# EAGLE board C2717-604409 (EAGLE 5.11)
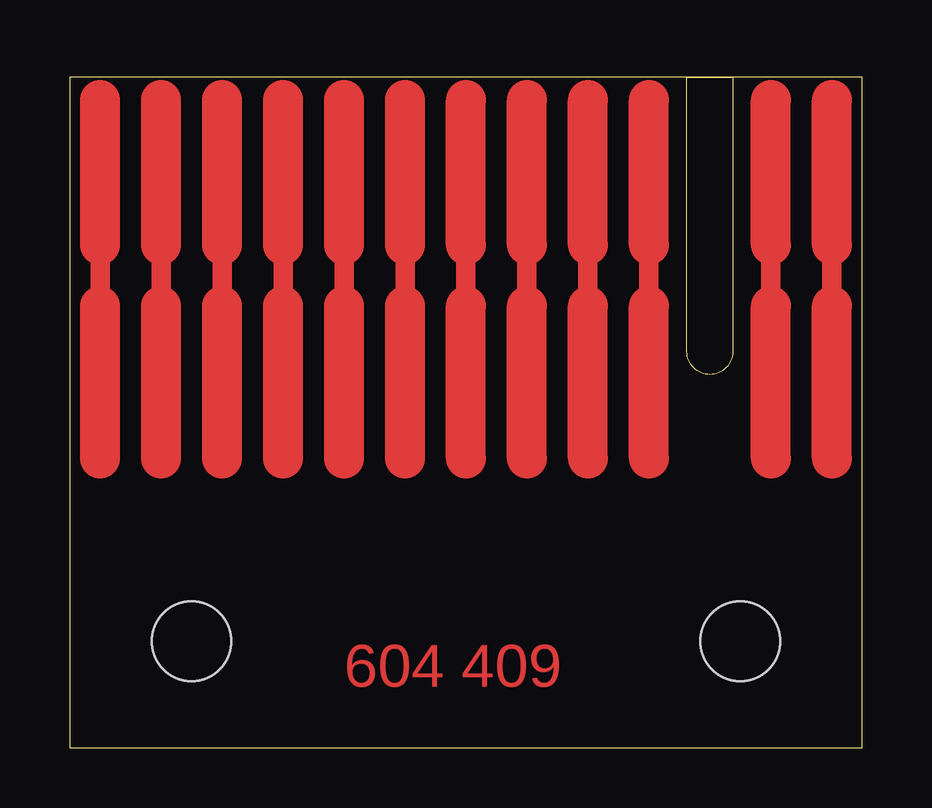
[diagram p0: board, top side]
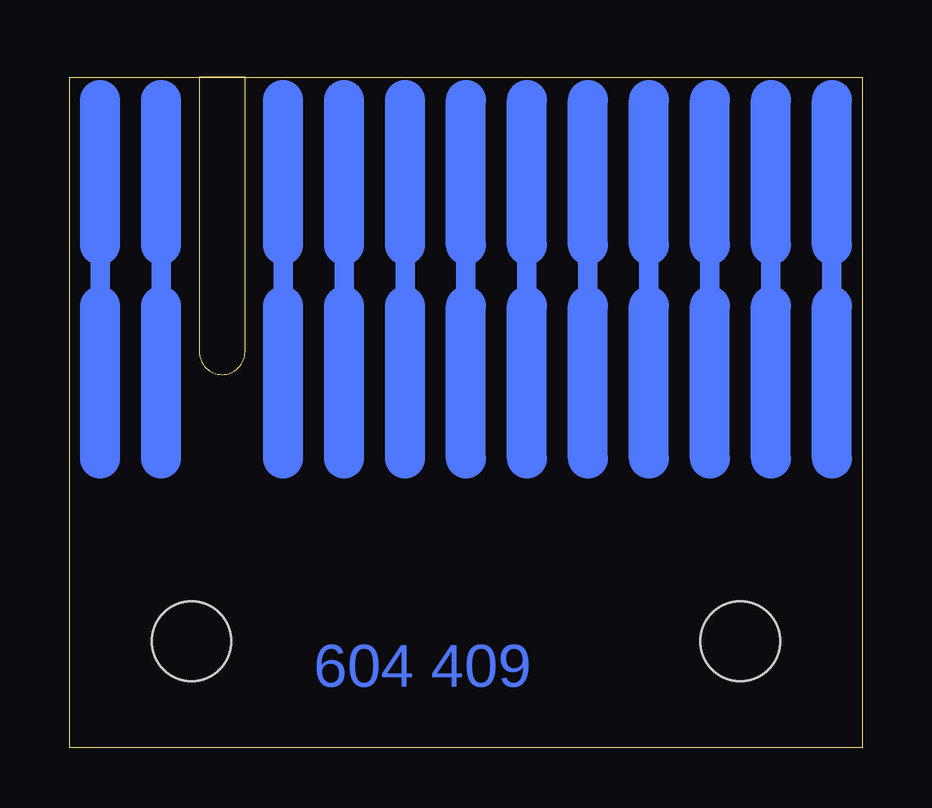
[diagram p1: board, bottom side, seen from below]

Size 33.02 x 27.94 mm. Coordinates in mm from the lower left corner, seen from the top.
Outline: 0,0 33.02,0 33.02,27.94 0,27.94 0,0
Copper layers (1*16): Top 0.0356mm / dielectric 1.5011mm / Bottom 0.0356mm
Design rules "LaenPCBOrder": minimum track width 6mil, minimum drill 13mil, track to track 6mil, track to pad 6mil, pad to pad 6mil, via to via 6mil, smd to smd 6mil, copper to edge 15mil, drill to drill 6mil, minimum pad ring 7mil, minimum via ring 7mil, stop-mask expansion 4mil, vias tented up to drill 0mil, thermal gap 10mil
Holes 3.3 mm at 5.08,4.45 27.94,4.45
Milling: 4 lines

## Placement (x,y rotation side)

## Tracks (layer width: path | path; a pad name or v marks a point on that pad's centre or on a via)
P1
  Bottom 0.813: 1.27,18.41 1.27,20.95
  Bottom 1.676: 1.27,20.95 1.27,26.99 | 1.27,12.06 1.27,18.41
P2
  Top 0.813: 1.27,18.41 1.27,20.95
  Top 1.676: 1.27,20.95 1.27,26.99 | 1.27,12.06 1.27,18.41
P3
  Bottom 0.813: 3.81,18.41 3.81,20.95
  Bottom 1.676: 3.81,20.95 3.81,26.99 | 3.81,12.06 3.81,18.41
P4
  Top 0.813: 3.81,18.41 3.81,20.95
  Top 1.676: 3.81,20.95 3.81,26.99 | 3.81,12.06 3.81,18.41
P5
  Bottom 0.813: 6.35,18.41 6.35,20.95
  Bottom 1.676: 6.35,20.95 6.35,26.99 | 6.35,12.06 6.35,18.41
P6
  Top 0.813: 6.35,18.41 6.35,20.95
  Top 1.676: 6.35,20.95 6.35,26.99 | 6.35,12.06 6.35,18.41
P7
  Bottom 0.813: 8.89,18.41 8.89,20.95
  Bottom 1.676: 8.89,20.95 8.89,26.99 | 8.89,12.06 8.89,18.41
P8
  Top 0.813: 8.89,18.41 8.89,20.95
  Top 1.676: 8.89,20.95 8.89,26.99 | 8.89,12.06 8.89,18.41
P9
  Bottom 0.813: 11.43,18.41 11.43,20.95
  Bottom 1.676: 11.43,20.95 11.43,26.99 | 11.43,12.06 11.43,18.41
P10
  Top 0.813: 11.43,18.41 11.43,20.95
  Top 1.676: 11.43,20.95 11.43,26.99 | 11.43,12.06 11.43,18.41
P11
  Bottom 0.813: 13.97,18.41 13.97,20.95
  Bottom 1.676: 13.97,20.95 13.97,26.99 | 13.97,12.06 13.97,18.41
P12
  Top 0.813: 13.97,18.41 13.97,20.95
  Top 1.676: 13.97,20.95 13.97,26.99 | 13.97,12.06 13.97,18.41
P13
  Bottom 0.813: 16.51,18.41 16.51,20.95
  Bottom 1.676: 16.51,20.95 16.51,26.99 | 16.51,12.06 16.51,18.41
P14
  Top 0.813: 16.51,18.41 16.51,20.95
  Top 1.676: 16.51,20.95 16.51,26.99 | 16.51,12.06 16.51,18.41
P15
  Bottom 0.813: 19.05,18.41 19.05,20.95
  Bottom 1.676: 19.05,20.95 19.05,26.99 | 19.05,12.06 19.05,18.41
P16
  Top 0.813: 19.05,18.41 19.05,20.95
  Top 1.676: 19.05,20.95 19.05,26.99 | 19.05,12.06 19.05,18.41
P17
  Bottom 0.813: 21.59,18.41 21.59,20.95
  Bottom 1.676: 21.59,20.95 21.59,26.99 | 21.59,12.06 21.59,18.41
P18
  Top 0.813: 21.59,18.41 21.59,20.95
  Top 1.676: 21.59,20.95 21.59,26.99 | 21.59,12.06 21.59,18.41
P19
  Bottom 0.813: 24.13,18.41 24.13,20.95
  Bottom 1.676: 24.13,20.95 24.13,26.99 | 24.13,12.06 24.13,18.41
P20
  Top 0.813: 24.13,18.41 24.13,20.95
  Top 1.676: 24.13,20.95 24.13,26.99 | 24.13,12.06 24.13,18.41
P23
  Bottom 0.813: 29.21,18.41 29.21,20.95
  Bottom 1.676: 29.21,20.95 29.21,26.99 | 29.21,12.06 29.21,18.41
P24
  Top 0.813: 29.21,18.41 29.21,20.95
  Top 1.676: 29.21,20.95 29.21,26.99 | 29.21,12.06 29.21,18.41
P25
  Bottom 0.813: 31.75,18.41 31.75,20.95
  Bottom 1.676: 31.75,20.95 31.75,26.99 | 31.75,12.06 31.75,18.41
P26
  Top 0.813: 31.75,18.41 31.75,20.95
  Top 1.676: 31.75,20.95 31.75,26.99 | 31.75,12.06 31.75,18.41

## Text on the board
Top: 604 409
Bottom: 604 409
